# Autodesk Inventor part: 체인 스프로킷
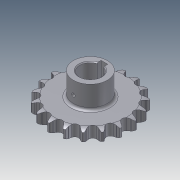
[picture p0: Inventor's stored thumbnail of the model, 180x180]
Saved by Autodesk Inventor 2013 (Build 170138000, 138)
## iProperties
Created: 2014-07
Part Number: 체인 스프로킷
Material: 강
Document SubType Name: Modeling
Designer: KYOUNG IL JANG
Density: 7.85 g/cm^3
Mass: 738.626 g
Surface Area: 236.854 cm^2
Volume: 94.0925 cm^3
Company: 한국ATC센터
Author: KYOUNG IL JANG
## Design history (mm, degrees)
sketch "이론적 톱니 프로파일"
  geometry: L1 (0, 0)-(0, 45.567); L2 (0, 0)-(14.795, 43.098); L3 (0, 45.567)-(14.795, 43.098); L4 (0, 45.567)-(5.661, 50.015); L5 (5.661, 50.015)-(-5.141, 45.406); L6 (-12.428, 43.493)-(-5.573, 46.417); L7 (-5.141, 45.406)-(-5.573, 46.417); L8 (5.573, 46.417)-(5.141, 45.406); L9 (0, 0)-(8.138, 48.771); A1 r 45.567 centre (0, 0) between (0, 45.567) and (14.795, 43.098); A2 r 49.445 centre (0, 0) between (7.302, 48.903) and (-7.302, 48.903); A3 r 4.545 centre (0, 45.567) between (-3.574, 42.758) and (3.574, 42.758); A4 r 7.453 centre (12.428, 43.493) between (7.302, 48.903) and (5.573, 46.417); A5 r 7.453 centre (-12.428, 43.493) between (-5.573, 46.417) and (-7.302, 48.903); A6 r 11.745 centre (5.661, 50.015) between (-5.141, 45.406) and (-3.574, 42.758); A7 r 11.745 centre (-5.661, 50.015) between (3.574, 42.758) and (5.141, 45.406); 2 further points
  constraints: 18 end point, 15 point on circle, 7 centre point, 3 coincident, 3 point on line, 3 symmetric about line, 3 tangent, 1 equal radius, 1 midpoint, 1 parallel, 1 vertical, 1 other
  dimensions: "d0" = 91.13301 diameter of A1 (computed from da_p, da_z); "d2" = 18.9474 deg angle of L2 L1 (computed from da_z); "d3" = 4.545 radius of A3 (= 0.5 x da_Dr + da_SC); "d10" = 128.158 deg angle of L4 L1 (computed from da_z); "d11" = 15.0526 deg angle of L5 L4 (computed from da_z); "d12" = 7.2 distance of L3.start L4.end (= 0.8 x da_Dr); "d13" = 11.745 distance of L4.end L5.end (= 1.3 x da_Dr + da_SC); "d14" = 12.6 distance of A4.centre L1.end (= 1.4 x da_Dr); "d23" = 4.5 distance from line of L9.end L3 (= da_Ha)
sketch "톱니 프로파일"
  geometry: L1 (0, 0)-(0, 45.567); L2 (0, 45.567)-(4.203, 43.837); L3 (0, 45.567)-(-4.203, 43.837); A1 r 4.545 centre (0, 45.567) between (-4.203, 43.837) and (4.203, 43.837); A2 r 22.68 centre (25.176, 35.206) between (7.12, 48.93) and (4.203, 43.837); A3 r 22.68 centre (-25.176, 35.206) between (-4.203, 43.837) and (-7.12, 48.93); A4 r 49.445 centre (0, 0) between (-7.12, 48.93) and (7.12, 48.93) reference; 1 further point
  constraints: 9 point on circle, 6 end point, 3 centre point, 2 tangent, 1 coincident, 1 equal radius, 1 vertical, 1 other
  dimensions: "d44" = 135.263 deg angle of L3 L2 (= da_Alfa); "d45" = 22.68 radius of A2 (= da_Re); "d46" = 4.545 radius of A1 (= da_Ri)
sketch "단면 프로파일"
  geometry: L1 (49.445, 0)-(-49.445, 0) reference; L2 (33.265, 6.65)-(-33.265, 6.65); L3 (-33.265, 6.65)-(-33.265, -6.65); L4 (-33.265, -6.65)-(33.265, -6.65); L5 (33.265, -6.65)-(33.265, 6.65); L6 (33.265, 6.65)-(49.445, 6.65); L7 (49.445, 6.65)-(49.445, -6.65); L8 (49.445, -6.65)-(33.265, -6.65); L9 (33.265, -6.65)-(33.265, 6.65); L10 (42.183, 6.65)-(0, 6.65); L11 (0, 6.65)-(0, -6.65); L12 (0, -6.65)-(42.183, -6.65); L13 (0, 6.65)-(0, -6.65); L14 (49.445, 4.775)-(49.445, -4.775); A1 r 15 centre (42.183, -8.35) between (49.445, 4.775) and (42.183, 6.65); A2 r 15 centre (42.183, 8.35) between (42.183, -6.65) and (49.445, -4.775); 2 further points
  constraints: 26 end point, 7 midpoint, 5 perpendicular, 4 parallel, 4 point on circle, 3 point on line, 3 symmetric about line, 2 centre point, 2 horizontal, 2 tangent, 1 collinear, 1 other
  dimensions: "d30" = 13.3 distance between parallel lines of L8 L6 (= da_Bf); "d31" = 66.53007 distance between parallel lines of L3 L5 (= da_Ds); "d32" = 13.3 distance between parallel lines of L4 L2 (= da_Bs); "d33" = 1.875 distance from line of L14.start L6 (= da_Ba); "d34" = 15 radius of A1 (= da_Rx); "d43" = 6.65 distance between parallel lines of L4 L1 (computed from da_k, da_pt, da_Bs)
revolve "슈라우드" stored, may be unused: angle "d36" = 90 deg
revolve "스트랜드" stored, may be unused: angle "d37" = 90 deg
extrude "이론적 톱니" cut sketch "이론적 톱니 프로파일" stored distance "d18" = 10; taper "d19" = 0 deg; dims "d49" = 0, "form_type" = 0 [user parameter]
extrude "톱니" cut sketch "톱니 프로파일" stored distance "d47" = 10; taper "d48" = 0 deg; dims "d50" = 10, "form_type" = 0 [user parameter]
node "타이밍 평면"
node "작업 평면3"
sketch "스케치5"
  geometry: C1 r 20 at (0, -45.567); 1 further point
  constraints: 1 centre point, 1 coincident
  dimensions: "d52" = 40 diameter of C1
extrude "돌출4" join sketch "스케치5" stored distance "d53" = 10; taper "d54" = 0 deg
sketch "스케치6"
  geometry: L1 (4, 11.843)-(4, 16.5); L2 (4, 16.5)-(-4, 16.5); L3 (-4, 16.5)-(-4, 11.843); A1 r 12.5 centre (0, 0) between (4, 11.843) and (-4, 11.843); 1 further point
  constraints: 6 end point, 2 parallel, 2 point on circle, 1 centre point, 1 coincident, 1 perpendicular, 1 vertical
  dimensions: "d55" = 25 diameter of A1; "d56" = 29 dimension on A1 L2 (computed from d55); "d57" = 8 distance of L1.end L2.end
extrude "돌출5" cut sketch "스케치6" stored distance "d58" = 10; taper "d59" = 0 deg
fillet "모깎기2" dims "d60" = 3
chamfer "모따기1" distance "d61" = 1; stored, may be unused: second distance "d62" = 2, angle "d63" = 45 deg
node "작업 평면4"
sketch "스케치7"
  geometry: L1 (-13.5, -13.3)-(13.5, -13.3) reference; 4 further points
  constraints: 1 vertical alignment
  dimensions: "d65" = 25 distance from line of point (0, 11.7) L1
hole "구멍1" sketch "스케치7" at (0, 11.7) diameter "d66" = 4.134; stored, may be unused: countersink angle "d70" = 90 deg, drill point angle "d72" = 118 deg; dims "d67" = 6, "d68" = 4, "d69" = 2, "d71" = 8
body "Solid1"
pattern_linear "스트랜드 패턴" dims "d40" = 24 (= da_pt)
pattern_circular "톱니 패턴" dims angle "d21" = 360 deg
other parameters: "da_p" = 15 [user parameter; used in 1 equation term], "da_Dr" = 9 [user parameter; used in 4 equation terms], "da_SC" = 0.045 [user parameter; used in 2 equation terms], "da_Ha" = 4.5 [user parameter; used in 1 equation term], "da_pt" = 24 [user parameter; used in 2 equation terms], "da_Bf" = 13.3 [user parameter; used in 1 equation term], "d28" = 0, "d29" = 0, "da_Ba" = 1.875 [user parameter; used in 1 equation term], "da_Rx" = 15 [user parameter; used in 1 equation term], "da_Ra" = 0.6 [user parameter], "da_Bs" = 13.3 [user parameter; used in 2 equation terms], "da_Ds" = 66.53007 [user parameter; used in 1 equation term], "d42" = 0, "da_Re" = 22.68 [user parameter; used in 1 equation term], "da_Ri" = 4.545 [user parameter; used in 1 equation term], "da_Alfa" = 135.263 deg [user parameter; used in 1 equation term]
